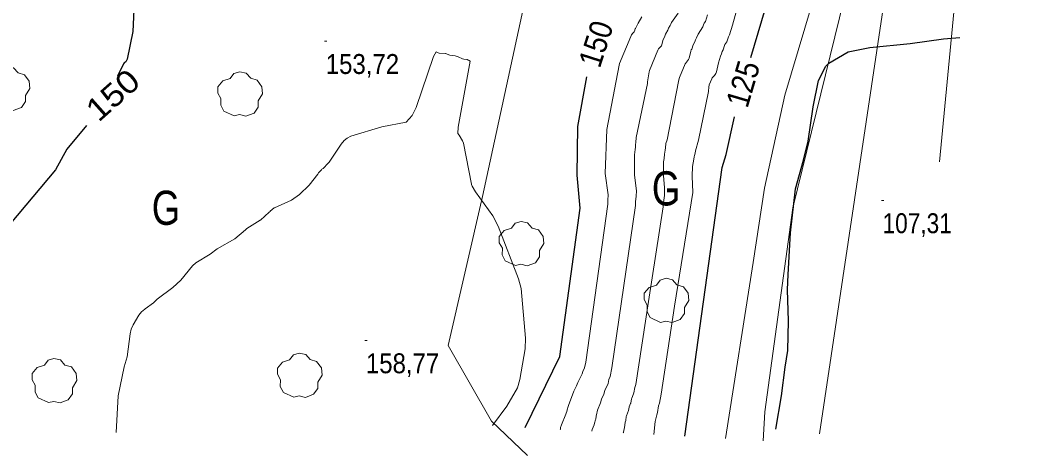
# Model space of a CAD drawing. Extents: x 480264 to 484872, y 4381275 to 4384491.
# Drawn here: x 480605 to 481054, y 4383606.4 to 4383797.7 of the extents above; entities that cross this region are included whole.
import ezdxf
from ezdxf.enums import TextEntityAlignment as Align

# ---------------------------------------------------------------- set-up
doc = ezdxf.new("R2010")
doc.units = 0
doc.header["$LTSCALE"] = 4
doc.linetypes.add('LONG_DASHED', pattern=[7.5, 6, -1.5])
for name, color, linetype, lineweight in [('25', 7, 'LONG_DASHED', 25), ('29', 7, 'Continuous', 13), ('51', 7, 'Continuous', 13), ('7', 7, 'Continuous', 13), ('8', 7, 'Continuous', 25), ('9', 7, 'Continuous', 13)]:
    doc.layers.add(name, color=color, linetype=linetype, lineweight=lineweight)
doc.layers.add('31', color=7, linetype='Continuous')

msp = doc.modelspace()

# ---------------------------------------------------------------- linework, layer by layer
at = {"layer": '25'}
msp.add_lwpolyline([(480936.86, 4383617.97), (480939.29, 4383632.62), (480940.88, 4383645.3), (480942.08, 4383652.68), (480942.4, 4383665.62), (480941.93, 4383679.28), (480942.23, 4383686), (480943.34, 4383704.37), (480945.47, 4383723.65), (480949.02, 4383736.31), (480950.99, 4383744.64), (480953.24, 4383759.68), (480955.53, 4383771.22), (480958.74, 4383777.6), (480960.06, 4383778.87), (480968.56, 4383783.95), (480978.18, 4383785.8), (480995.8, 4383787.6), (481010.54, 4383789.64), (481017.64, 4383790.18)], dxfattribs=at)
at = {"layer": '29'}
for points in [[(480596.76, 4383758.12), (480592.22, 4383760.24), (480590.81, 4383762.78), (480590.91, 4383765.76), (480589.54, 4383768.17), (480589.58, 4383770.92), (480591.74, 4383773.52), (480594.93, 4383774.52), (480596.58, 4383776.71), (480599.15, 4383777.54), (480602.01, 4383776.89), (480603.96, 4383774.62), (480606.77, 4383773.8), (480608.9, 4383770.95), (480609.14, 4383767.82), (480607.26, 4383764.67), (480607.26, 4383761.99), (480605.44, 4383759.38), (480601.82, 4383758.04), (480599.05, 4383758.67)], [(480698.96, 4383755.74), (480694.42, 4383757.86), (480693.01, 4383760.4), (480693.11, 4383763.38), (480691.74, 4383765.79), (480691.78, 4383768.54), (480693.94, 4383771.14), (480697.13, 4383772.14), (480698.78, 4383774.33), (480701.35, 4383775.16), (480704.21, 4383774.51), (480706.16, 4383772.24), (480708.97, 4383771.42), (480711.1, 4383768.57), (480711.34, 4383765.44), (480709.46, 4383762.29), (480709.46, 4383759.61), (480707.64, 4383757), (480704.02, 4383755.66), (480701.25, 4383756.29)], [(480822.55, 4383689.95), (480818.01, 4383692.07), (480816.6, 4383694.61), (480816.7, 4383697.59), (480815.33, 4383700), (480815.37, 4383702.75), (480817.53, 4383705.35), (480820.72, 4383706.35), (480822.37, 4383708.54), (480824.94, 4383709.37), (480827.8, 4383708.72), (480829.75, 4383706.45), (480832.56, 4383705.63), (480834.69, 4383702.78), (480834.93, 4383699.65), (480833.05, 4383696.5), (480833.05, 4383693.82), (480831.23, 4383691.21), (480827.61, 4383689.87), (480824.84, 4383690.5)], [(480886.2, 4383664.95), (480881.66, 4383667.07), (480880.25, 4383669.61), (480880.35, 4383672.59), (480878.98, 4383675), (480879.02, 4383677.75), (480881.18, 4383680.35), (480884.37, 4383681.35), (480886.02, 4383683.54), (480888.59, 4383684.37), (480891.45, 4383683.72), (480893.4, 4383681.45), (480896.21, 4383680.63), (480898.34, 4383677.78), (480898.58, 4383674.65), (480896.7, 4383671.5), (480896.7, 4383668.82), (480894.88, 4383666.21), (480891.26, 4383664.87), (480888.49, 4383665.5)], [(480725.1, 4383632.09), (480720.56, 4383634.21), (480719.15, 4383636.75), (480719.25, 4383639.73), (480717.88, 4383642.14), (480717.92, 4383644.89), (480720.08, 4383647.49), (480723.27, 4383648.49), (480724.92, 4383650.68), (480727.49, 4383651.51), (480730.35, 4383650.86), (480732.3, 4383648.59), (480735.11, 4383647.77), (480737.24, 4383644.92), (480737.48, 4383641.79), (480735.6, 4383638.64), (480735.6, 4383635.96), (480733.78, 4383633.35), (480730.16, 4383632.01), (480727.39, 4383632.64)], [(480617.36, 4383629.71), (480612.82, 4383631.83), (480611.41, 4383634.37), (480611.51, 4383637.35), (480610.14, 4383639.76), (480610.18, 4383642.51), (480612.34, 4383645.11), (480615.53, 4383646.11), (480617.18, 4383648.3), (480619.75, 4383649.13), (480622.61, 4383648.48), (480624.56, 4383646.21), (480627.37, 4383645.39), (480629.5, 4383642.54), (480629.74, 4383639.41), (480627.86, 4383636.26), (480627.86, 4383633.58), (480626.04, 4383630.97), (480622.42, 4383629.63), (480619.65, 4383630.26)]]:
    msp.add_lwpolyline(points, close=True, dxfattribs=at)
at = {"layer": '51'}
msp.add_lwpolyline([(480826.37, 4383805.45), (480807.93, 4383720.33), (480792.92, 4383654.78), (480811.87, 4383621.48), (480827.76, 4383606.43)], dxfattribs=at)
at = {"layer": '7'}
for p, q in [((480738.64, 4383788.53), (480739.64, 4383788.53)), ((480983.21, 4383718.55), (480984.21, 4383718.55)), ((480756.27, 4383656.98), (480757.27, 4383656.98))]:
    msp.add_line(p, q, dxfattribs=at)
at = {"layer": '8'}
for points in [[(480925.86, 4383781.42), (480964.73, 4383912.62), (480991.03, 4384036.1), (480997.56, 4384143.26)], [(480655.4, 4383815.31), (480654.42, 4383792.89), (480651.9, 4383780.7)], [(480651.9, 4383780.7), (480651.28, 4383779.49), (480650.82, 4383779.27), (480650.59, 4383779.08), (480650.22, 4383778.62), (480647.72, 4383773.18)], [(480826.79, 4383618.82), (480841.97, 4383649.93), (480850.88, 4383715.18), (480849.54, 4383729.69), (480849.9, 4383751.05), (480853.85, 4383772.88)], [(480896.88, 4383614.89), (480913.32, 4383733.06), (480915.04, 4383738.7), (480918.64, 4383755.32)], [(480633.96, 4383751.52), (480625.4, 4383741.05), (480620.41, 4383731.99), (480600.54, 4383708.28), (480597.98, 4383701.67), (480591.76, 4383689.89), (480591.22, 4383687.99), (480588.8, 4383674.43), (480590.76, 4383663.74), (480590.6, 4383655.79), (480590.05, 4383652.93), (480589.93, 4383650.98), (480590.76, 4383638.5), (480590.5, 4383636.18), (480582.6, 4383614.4)]]:
    msp.add_lwpolyline(points, dxfattribs=at)
at = {"layer": '9'}
for points in [[(480914.76, 4383613.89), (480926.88, 4383691.28), (480931.88, 4383724.01), (480940.74, 4383764.83), (480955.36, 4383814.11), (480979.08, 4383905.22), (481017.6, 4384142.1), (481017.94, 4384143.21)], [(481087.56, 4384143.04), (481080.17, 4384122.99), (481066.17, 4384097.54), (481054.02, 4384061), (481052.2, 4384021.9), (481047.46, 4383998.19), (481046.95, 4383997.07), (481046.65, 4383996.58), (481046.15, 4383996.01), (481045.41, 4383995.36), (481044.56, 4383994.84), (481040.72, 4383993.42), (481039.99, 4383993.01), (481039.14, 4383992.3), (481038.6, 4383991.74), (481038.02, 4383990.97), (481037.92, 4383990.81), (481037.65, 4383990.23), (481028.96, 4383952.39), (481021.17, 4383932.94), (481011.98, 4383915.23), (480983.95, 4383803.15), (480956.08, 4383616.02)], [(481008.76, 4383735.49), (481019.19, 4383844.21), (481025.42, 4383870.86), (481034.4, 4383894.2), (481036.96, 4383898.02), (481037.75, 4383898.92), (481038.26, 4383899.16), (481038.42, 4383899.21), (481041.05, 4383899.81), (481041.71, 4383900.08), (481042.91, 4383900.79), (481043.87, 4383901.56), (481044.65, 4383902.43), (481045.12, 4383903.11), (481045.64, 4383904.09), (481047.69, 4383911.19), (481048.6, 4383912.95), (481064.67, 4383933.66), (481085.85, 4383965.55), (481086.55, 4383967.45)], [(480979.2, 4383857.4), (480944.24, 4383715.26), (480931.96, 4383625.71), (480931.32, 4383612.96)], [(480919.63, 4383802.47), (480917.83, 4383795.57), (480916.42, 4383791.3), (480916.01, 4383790.42), (480915.44, 4383788.73), (480915.25, 4383788.32), (480914.46, 4383787.05), (480914.27, 4383786.64), (480913.65, 4383784.72), (480913.33, 4383784.01), (480912.99, 4383782.96), (480912.54, 4383781.93), (480911.6, 4383779.06), (480910.81, 4383775.14), (480910.51, 4383774.41), (480909.82, 4383773.47), (480909.03, 4383772.67), (480908.92, 4383772.52), (480908.65, 4383772.03), (480907.57, 4383769.44), (480907.51, 4383769.24), (480907.38, 4383768.56), (480907.28, 4383766.49), (480902.91, 4383745.1), (480901.57, 4383740.44), (480901.41, 4383739.35), (480901.13, 4383738.32), (480901.03, 4383737.69), (480900.77, 4383736.64), (480900.26, 4383733.44), (480900.13, 4383729.3), (480900.32, 4383722.11), (480892.35, 4383672.03), (480886.44, 4383633.38), (480885.75, 4383629.43), (480885.34, 4383628.27), (480884.84, 4383625.38), (480884.51, 4383624.38), (480884.19, 4383622.54), (480883.8, 4383621.36), (480883.19, 4383615.66)], [(480842.15, 4383617.96), (480842.19, 4383618.08), (480842.28, 4383618.67), (480842.31, 4383618.78), (480842.72, 4383619.87), (480842.95, 4383620.7), (480844.23, 4383623.84), (480845.02, 4383625.81), (480845.16, 4383626.59), (480845.64, 4383628), (480845.73, 4383628.43), (480848.15, 4383634.72), (480849.34, 4383637.13), (480849.87, 4383638.56), (480851.74, 4383642.29), (480852.05, 4383643.33), (480852.77, 4383644.99), (480853.34, 4383647.45), (480863.09, 4383716.88), (480863.01, 4383718.71), (480863.18, 4383720.99), (480861.93, 4383730.4), (480862.54, 4383749.7), (480867.99, 4383778.01), (480868.23, 4383778.81), (480873.11, 4383790.66), (480873.44, 4383791.3), (480874.05, 4383792.11), (480874.57, 4383792.68), (480874.76, 4383792.97), (480875.09, 4383794.01), (480875.15, 4383794.17), (480876.35, 4383796.54), (480877.93, 4383799.32)], [(480893.97, 4383800.93), (480891.04, 4383796.78), (480890.69, 4383796.07), (480890.46, 4383795.48), (480889.73, 4383794.22), (480889.41, 4383793.47), (480888.41, 4383791.67), (480887.89, 4383790.34), (480887.35, 4383789.24), (480887.22, 4383788.83), (480886.78, 4383787.03), (480886.55, 4383786.59), (480885.35, 4383785.14), (480885.04, 4383784.61), (480881.34, 4383775.69), (480881.17, 4383775.09), (480880.51, 4383770.7), (480880.47, 4383769.92), (480875.52, 4383746.3), (480875.36, 4383744.01), (480875.21, 4383743.1), (480875.12, 4383741.95), (480874.97, 4383740.91), (480874.82, 4383738.65), (480874.7, 4383729.74), (480875.56, 4383722.83), (480875.5, 4383720.5), (480875.21, 4383717.93), (480875.23, 4383716.29), (480864.72, 4383644.98), (480863.99, 4383641.21), (480863.49, 4383639.89), (480863.11, 4383638.18), (480861.66, 4383634.99), (480861.26, 4383633.42), (480860.26, 4383631.22), (480859.78, 4383629.61), (480858.52, 4383626.34), (480858.36, 4383625.63)], [(480869.83, 4383616.41), (480869.9, 4383616.64), (480870.04, 4383617.54), (480870.41, 4383618.69), (480870.68, 4383621.07), (480870.88, 4383621.87), (480871.12, 4383623.64), (480871.18, 4383623.88), (480872.06, 4383626.31), (480872.37, 4383627.73), (480872.42, 4383627.89), (480873.01, 4383629.3), (480873.07, 4383629.5), (480873.45, 4383631.41), (480873.52, 4383631.64), (480874.33, 4383633.54), (480874.49, 4383634.07), (480874.89, 4383636.32), (480875.28, 4383637.6), (480880.96, 4383674.11), (480887.37, 4383715.7), (480887.39, 4383716.48), (480887.86, 4383720.75), (480887.97, 4383724.16), (480887.42, 4383729.47), (480887.49, 4383735.59), (480887.72, 4383737.07), (480887.89, 4383738.93), (480888.08, 4383739.82), (480888.17, 4383740.71), (480888.39, 4383741.68), (480888.58, 4383743.57), (480889.05, 4383745.2), (480894.07, 4383770.8), (480894.34, 4383772.17), (480894.46, 4383772.57), (480896.98, 4383778.56), (480897.11, 4383778.78), (480898.53, 4383780.5), (480898.79, 4383781.08), (480899.48, 4383784.15), (480899.68, 4383784.71), (480899.89, 4383785.13), (480900.55, 4383786.98), (480901.22, 4383788.26), (480901.53, 4383789.11), (480902.02, 4383790.03), (480902.66, 4383791.71), (480904.7, 4383794.83), (480905.23, 4383796.16), (480905.35, 4383796.43), (480905.9, 4383797.28), (480906.87, 4383800.12)], [(480812.38, 4383619.63), (480818.64, 4383628.16), (480823.35, 4383636.2), (480824.42, 4383639.91), (480826.66, 4383653.38), (480826.87, 4383658.07), (480824.95, 4383679.87), (480823.75, 4383684.11), (480814.89, 4383707.19), (480812.53, 4383711.73), (480804.86, 4383722.29), (480803.49, 4383724.84), (480803.2, 4383725.62), (480803.2, 4383725.66), (480803.2, 4383725.67), (480803.18, 4383725.67), (480799.66, 4383743.74), (480799.25, 4383744.74), (480797.79, 4383747.32), (480797.16, 4383747.97), (480797.26, 4383750.74), (480802.63, 4383779.79), (480801.83, 4383780.28), (480801.42, 4383780.42), (480801.29, 4383780.45), (480799.75, 4383780.6), (480799.26, 4383780.75), (480797.22, 4383781.68), (480795.99, 4383782.11), (480793.63, 4383782.48), (480791.79, 4383783.09), (480791.53, 4383783.14), (480788.99, 4383783.3), (480788.46, 4383783.44), (480787.7, 4383783.84), (480786.46, 4383781.9), (480778.78, 4383759.4), (480777.1, 4383755.9), (480774.47, 4383753.04), (480763.73, 4383750.94), (480750.08, 4383746.83), (480748.6, 4383745.97), (480747.28, 4383744.89), (480745.87, 4383743.33), (480740.66, 4383735.42), (480740.25, 4383734.91), (480737.97, 4383732.61), (480737.42, 4383732.27), (480737.21, 4383732.08), (480735.98, 4383730.73), (480735.58, 4383730.05), (480731.8, 4383725.21), (480727.63, 4383721.16), (480724.02, 4383718.67), (480716.66, 4383715.34), (480716.47, 4383715.31), (480714.72, 4383713.9), (480714.72, 4383713.87), (480714.67, 4383713.74), (480714.32, 4383713.37), (480710.41, 4383709.93), (480710.38, 4383709.94), (480710.36, 4383709.94), (480710.34, 4383709.92), (480710.31, 4383709.9), (480710.31, 4383709.88), (480710.29, 4383709.85), (480704.46, 4383706.2), (480703.94, 4383705.66), (480699.15, 4383701.69), (480691.4, 4383697.27), (480688.39, 4383694.95), (480682.07, 4383691.18), (480680.56, 4383689.77), (480675.54, 4383683.53), (480671.92, 4383680.27), (480665.12, 4383675.24), (480663.43, 4383673.5), (480659.83, 4383670.91), (480659.64, 4383670.85), (480658.23, 4383669.57), (480657.02, 4383668.08), (480654.5, 4383663.96), (480653.68, 4383661.97), (480653.15, 4383659.91), (480651.95, 4383649.81), (480651.93, 4383649.78), (480651.93, 4383649.77), (480651.93, 4383649.76), (480650.58, 4383645.5), (480647.99, 4383632.68), (480647.05, 4383616.61)], [(480858.36, 4383625.63), (480858.27, 4383625.01), (480857.92, 4383623.81), (480857.74, 4383622.44), (480857.66, 4383622.1), (480857.13, 4383620.69), (480856.97, 4383619.94), (480856.14, 4383617.84), (480856.02, 4383617.18)]]:
    msp.add_lwpolyline(points, dxfattribs=at)

# ---------------------------------------------------------------- texts
at = {"layer": '31', "width": 0.8}
for p in [(480888.62, 4383716.37), (480668.95, 4383707.85)]:
    msp.add_text('G', height=15, dxfattribs=at).set_placement(p, align=Align.CENTER)
at = {"layer": '7'}
for s, width, p in [('153,72', 0.9, (480739.14, 4383774.16)), ('107,31', 0.85, (480983.71, 4383704.18)), ('158,77', 0.9, (480756.77, 4383642.61))]:
    msp.add_text(s, height=8.75, dxfattribs=dict(at, width=width)).set_placement(p)
at = {"layer": '8'}
for s, rotation, width, p in [('150', 72.175, 0.9, (480862.575, 4383785.854)), ('125', 73.497, 0.9, (480927.207, 4383768.365)), ('150', 41.634, 1.15, (480648.893, 4383761.168))]:
    msp.add_text(s, height=10, rotation=rotation, dxfattribs=dict(at, width=width)).set_placement(p, align=Align.CENTER)

doc.saveas('drawing.dxf')
